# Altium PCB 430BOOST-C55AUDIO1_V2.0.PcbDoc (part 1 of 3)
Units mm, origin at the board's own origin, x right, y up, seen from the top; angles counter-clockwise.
Board outline 50.8 x 84 mm, 4 copper layers (Top Layer, GND, POW, Bottom Layer); 272 components, 169 nets, 833 pads, 607 vias.
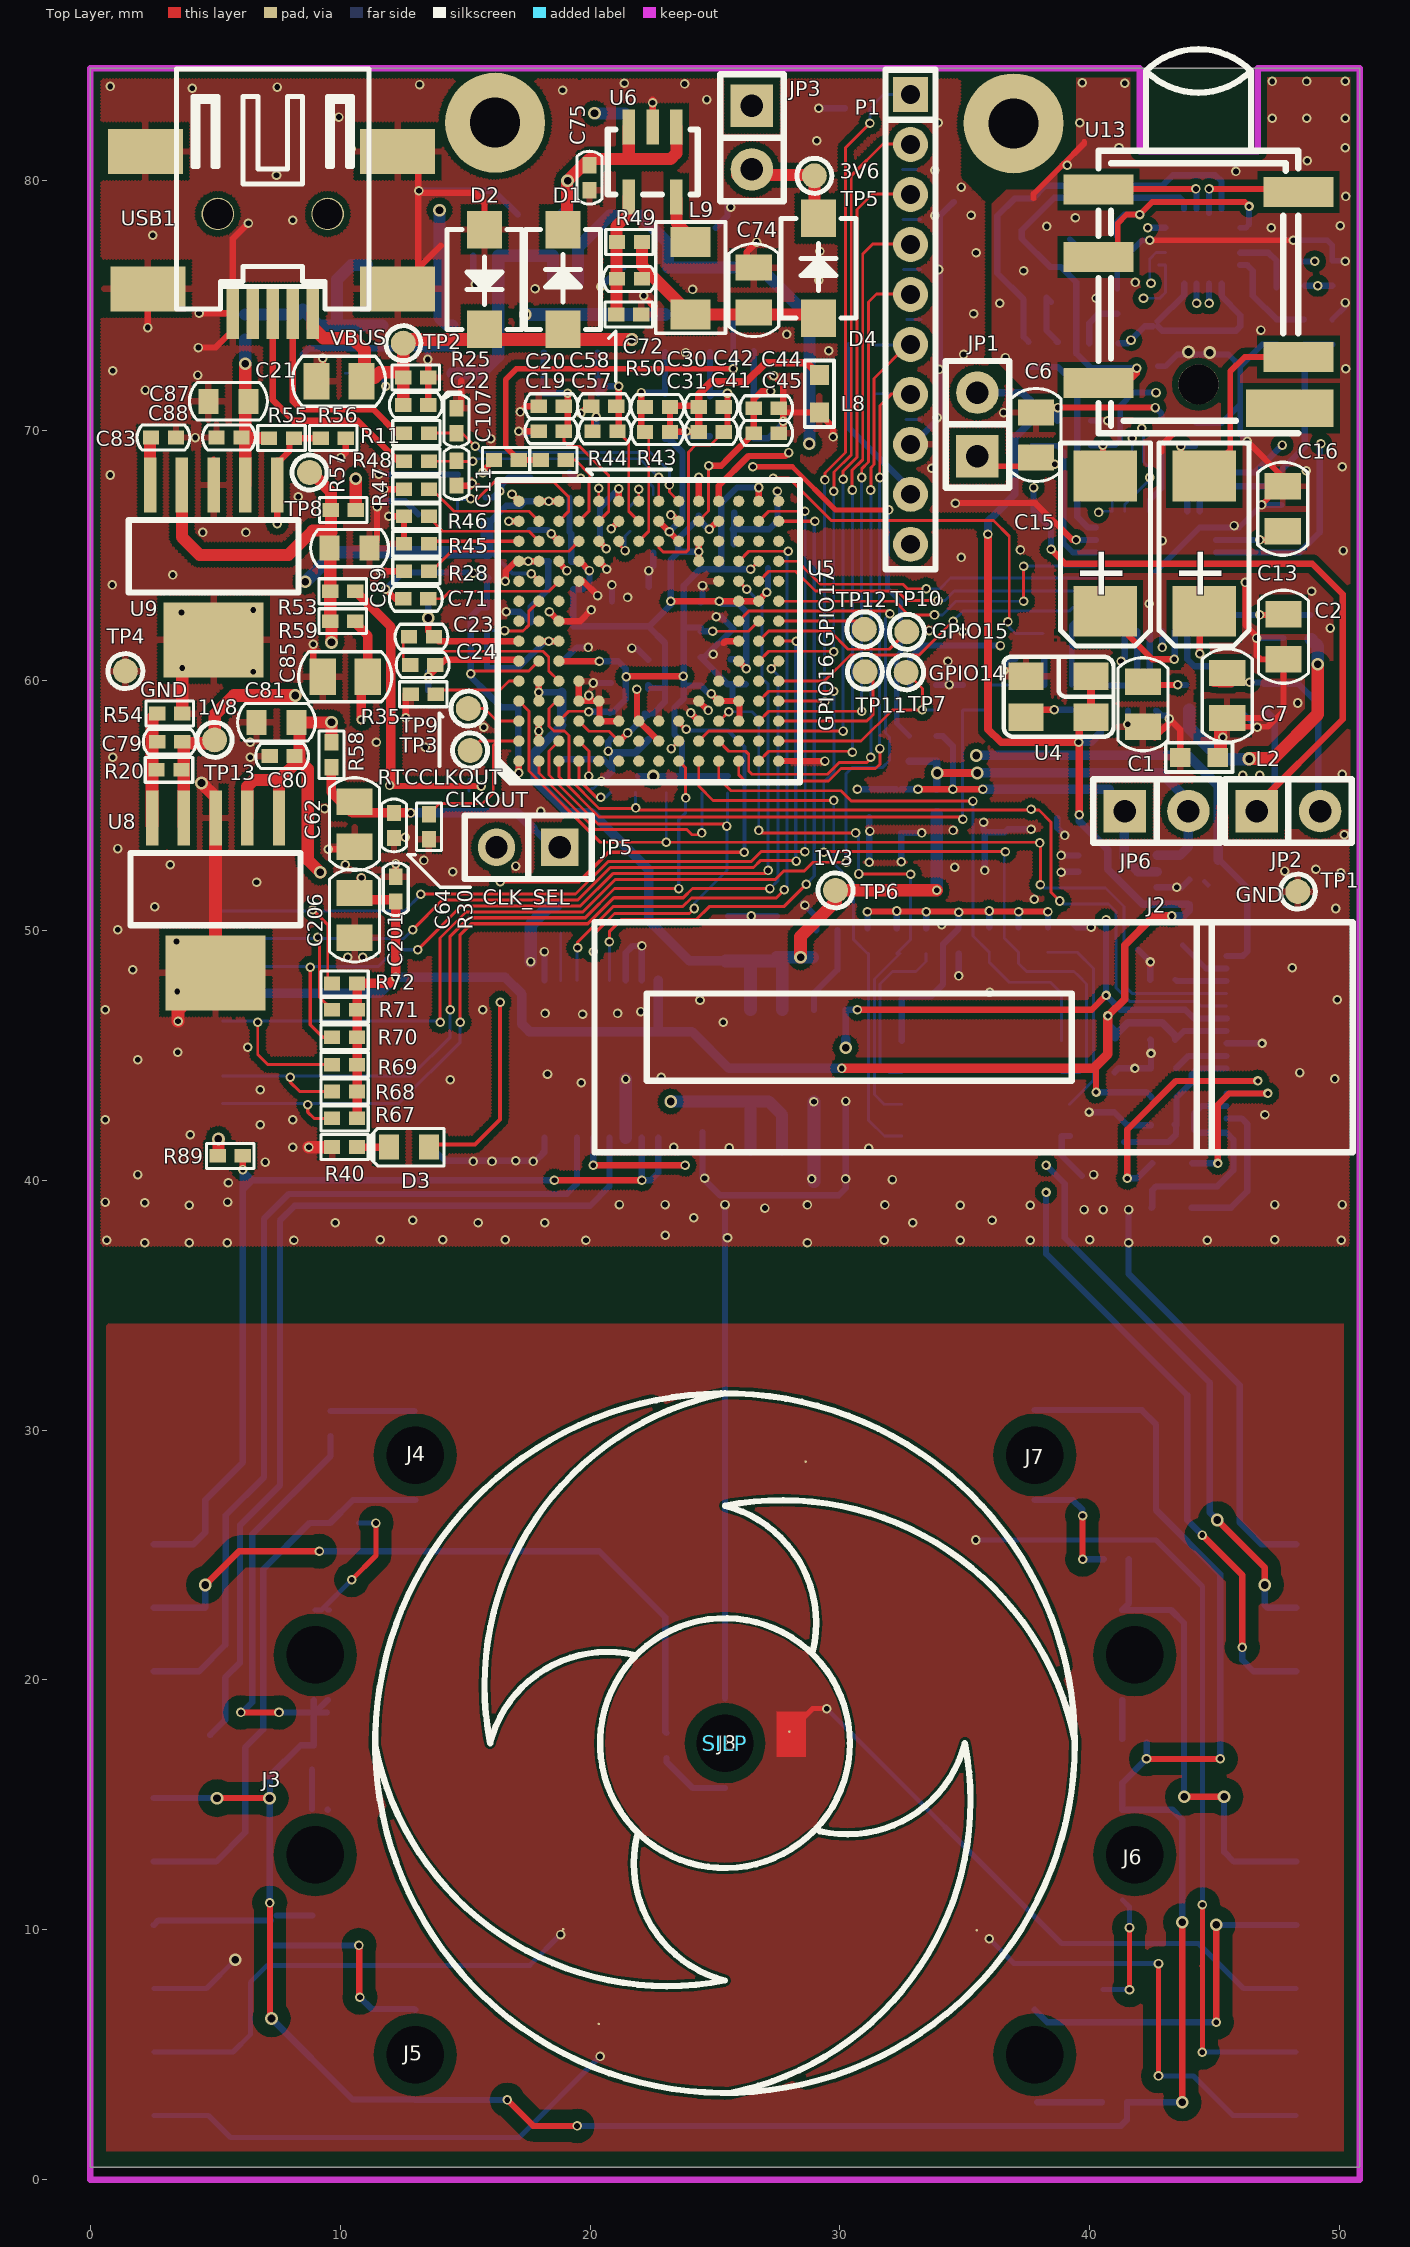
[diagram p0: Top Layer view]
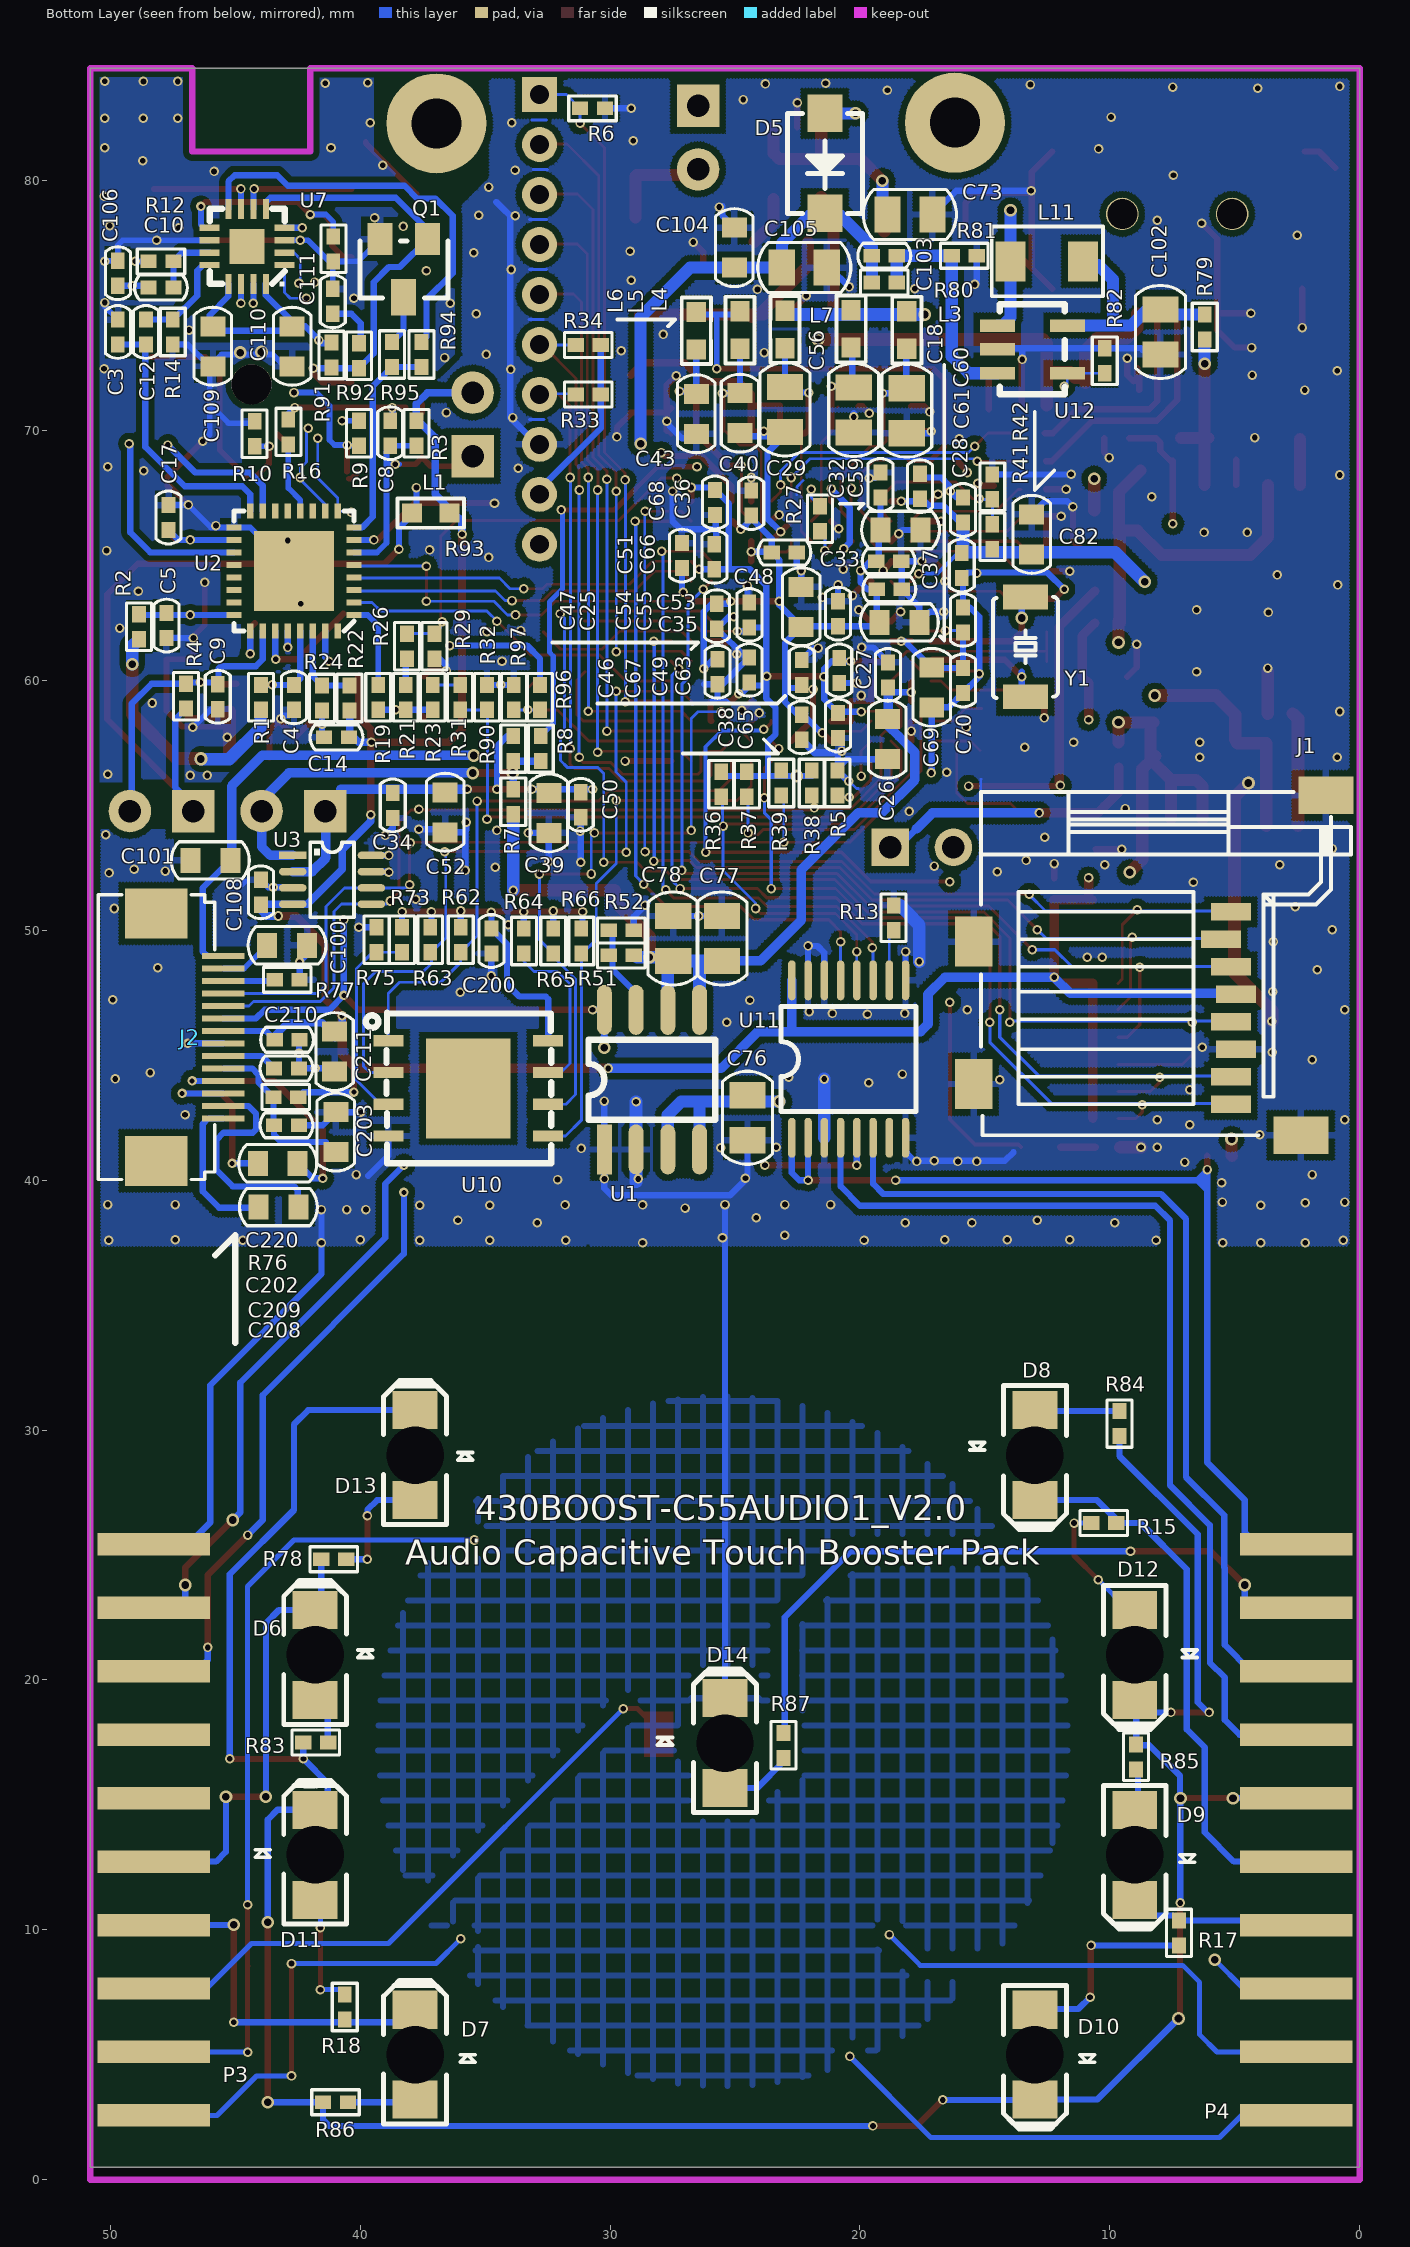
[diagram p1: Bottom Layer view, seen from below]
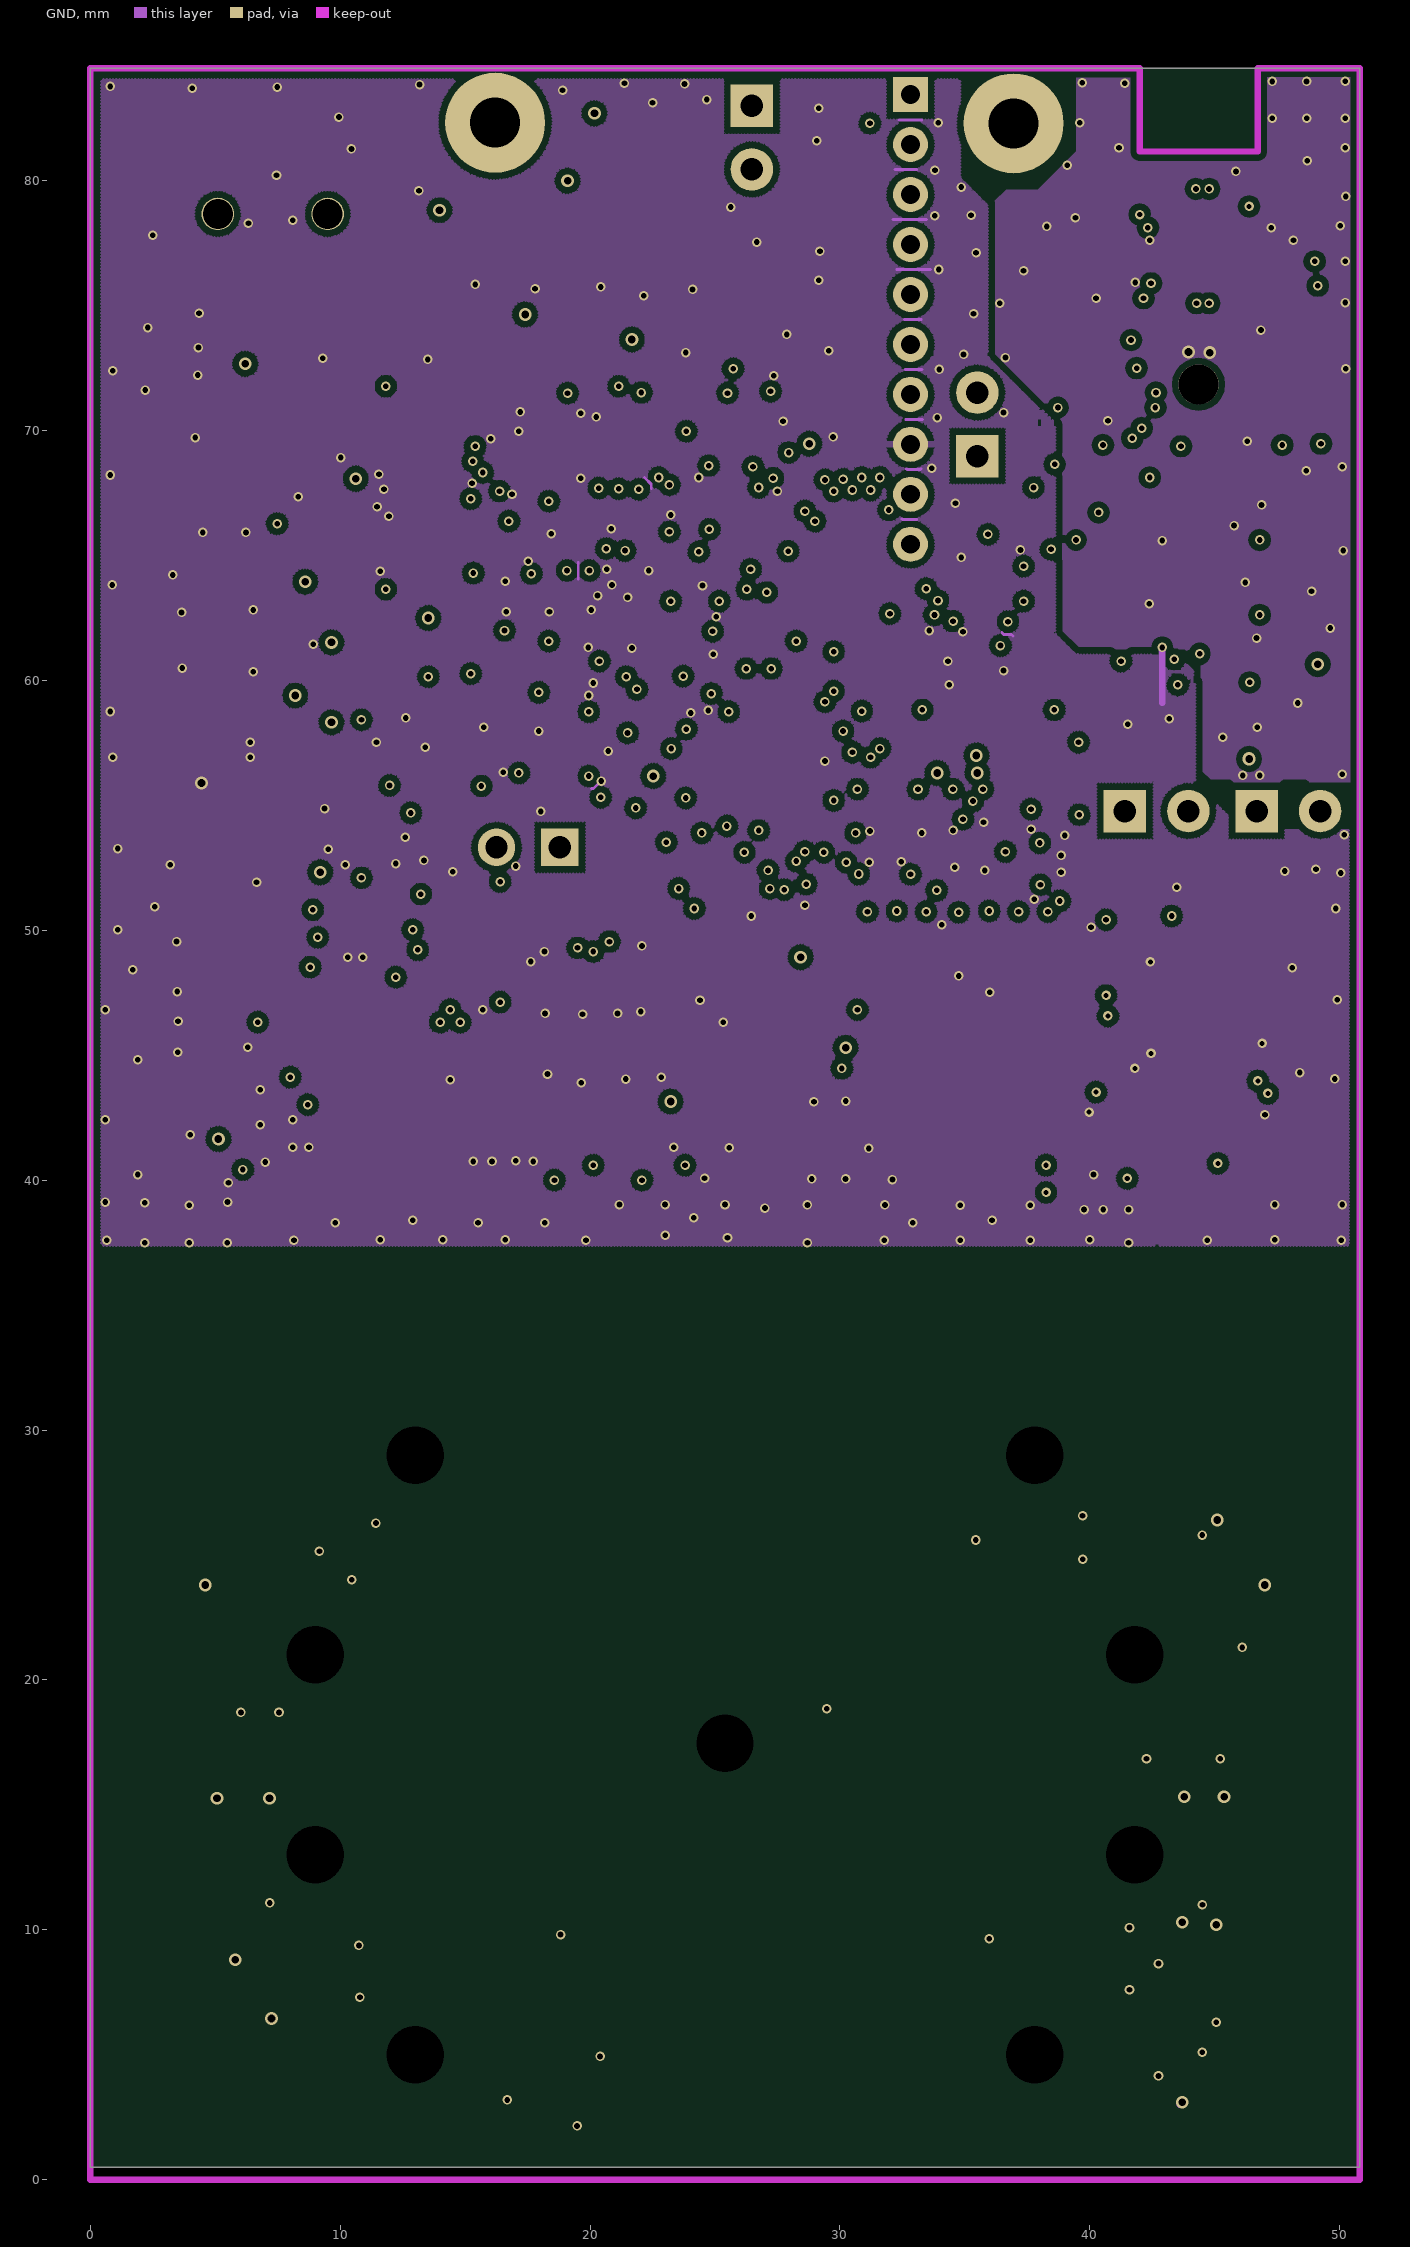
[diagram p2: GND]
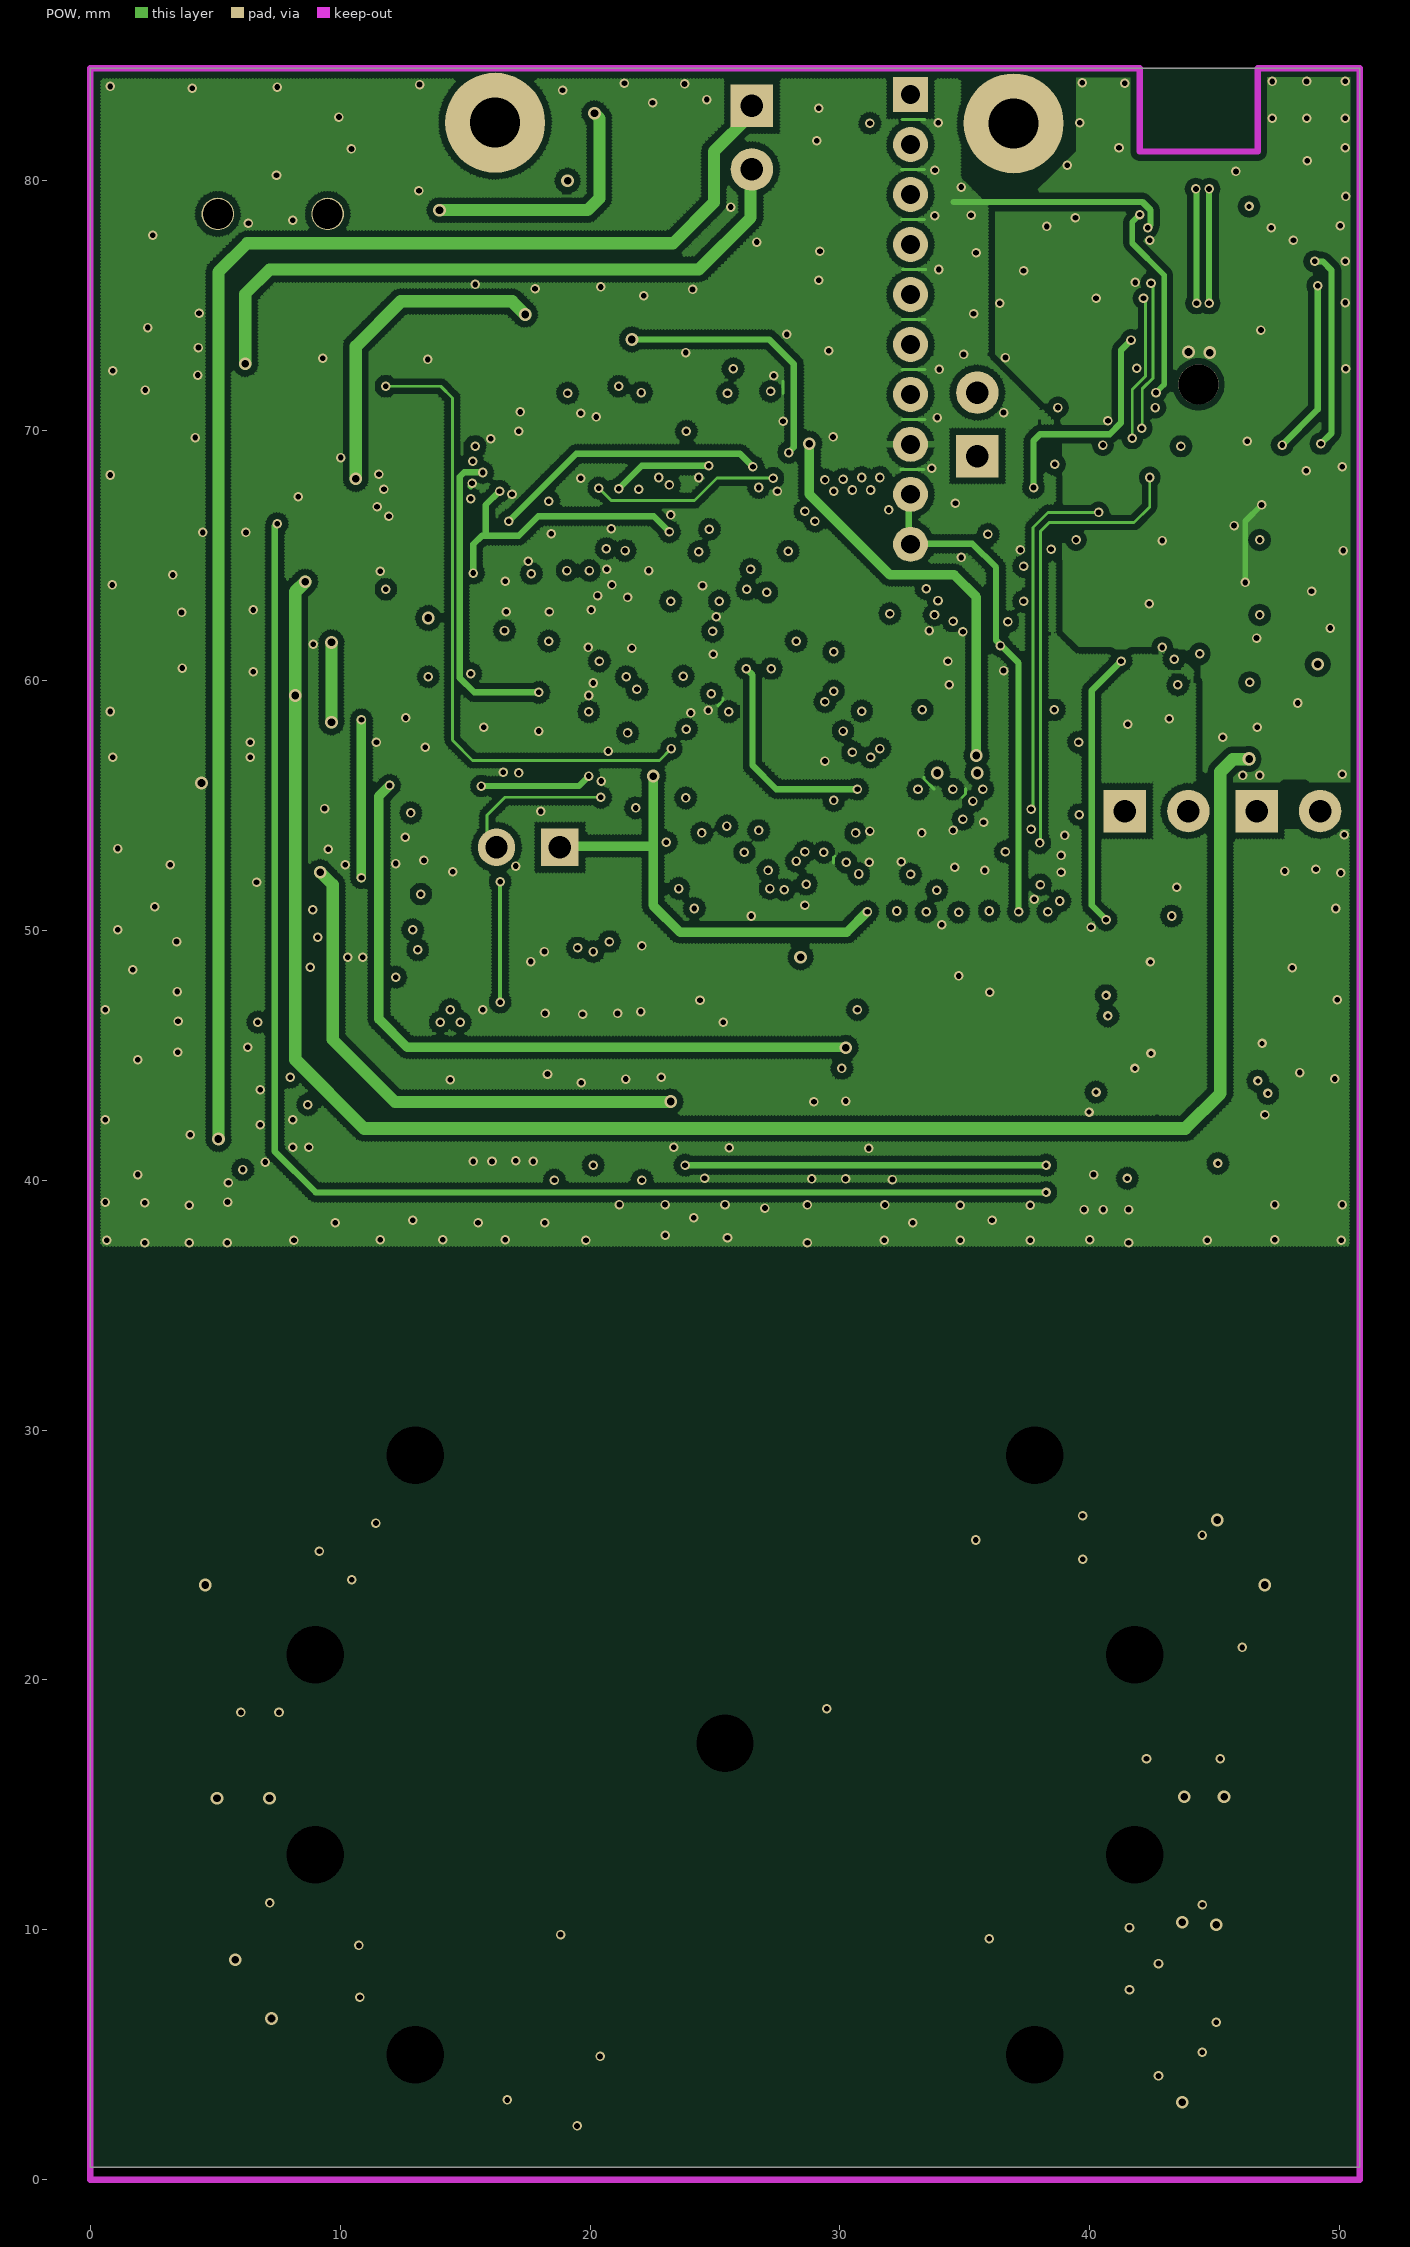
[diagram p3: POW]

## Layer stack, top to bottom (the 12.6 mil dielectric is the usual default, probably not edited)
Top Layer: signal copper 0.0356
Dielectric: core 0.32, FR-4, Dk 4.8
GND: signal copper 0.0356
Dielectric: prepreg 0.32, FR-4, Dk 4.8
POW: signal copper 0.0356
Dielectric: core 0.32, FR-4, Dk 4.8
Bottom Layer: signal copper 0.0356

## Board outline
0,84.5 0,0.5 50.8,0.5 50.8,84.5 0,84.5

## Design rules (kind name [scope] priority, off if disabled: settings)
Clearance Clearance_1 [IsBoard + InPolygon] p1: gap=0.25
Clearance [All] p2: gap=0.114
ComponentClearance [All] p1 off: gap=0.254 collisioncheckmode=3 verticalgap=0.254 showdistances=FALSE
FabricationTestPointUsage TestPointUsage [All] p1: valid=0 allowmultiple=FALSE
FabricationTestpoint Testpoint [(IsPad And (OnTopLayer Or OnBottomLayer))] p1: side=3 testpointundercomponent=TRUE minsize=1.016 maxsize=2.54 preferedsize=1.524 minholesize=0 maxholesize=1.016 preferedholesize=0.813 testpointgrid=0.025 allowsidetop=TRUE allowsidebottom=TRUE usegrid=TRUE gridtolerance=0
Height [All] p1 off: minheight=0 maxheight=25.4 prefheight=12.7
HoleSize [All] p1 off: absolutevalues=TRUE maxlimit=2.54 minlimit=0.025 maxpercent=80.000 minpercent=20.000
HoleToHoleClearance [All] p1 off: gap=0.254 allowstackedmicrovias=TRUE
LayerPairs [All] p1 off: enforce=TRUE
MinimumSolderMaskSliver [All] p1 off: minsoldermaskwidth=0.254
NetAntennae [All] p1 off: netantennaetolerance=0
PolygonConnect PolygonConnect_1 [IsVia + InPolygon] p1: connectstyle=Direct reliefconductorwidth=0.254 reliefentries=4 polygonreliefangle="90 Angle"
PolygonConnect [All] p2: connectstyle=Relief reliefconductorwidth=0.254 reliefentries=4 polygonreliefangle="90 Angle"
RoutingVias [All] p1: holewidth=0.229 width=0.381 viastyle="Through Hole" minholewidth=0.203 minwidth=0.381 maxholewidth=0.406 maxwidth=0.762
SilkToSilkClearance [All] p1 off: silktosilkclearance=0.254
SilkscreenOverComponentPads [All] p1 off: minsilkscreentomaskgap=0.254
SolderMaskExpansion [All] p1: expansion=0.102
Width [All] p1: maxlimit=4 minlimit=0.102 preferedwidth=0.25
17 further rules are at their usual default settings.

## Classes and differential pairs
component class 430BOOST-C55XAUDIO1_AIC3204: C1 C2 C3 C4 C5 C6 C7 C8 C9 C10 C12 C13 C14 C15 C16 C17 C106 D6 D7 D8 D9 D10 D11 D12 D13 D14 J3 J4 J5 J6 J7 J8 JP1 JP2 L1 L2 R1 R2 R3 R4 R9 R10 R12 R14 R15 R16 R17 R18 R19 R21 R22 R23 R24 R78 R83 R84 R85 R86 R87 TP1 U2 U4
component class 430BOOST-C55XAUDIO1_MCU_1: C11 C18 C19 C20 C21 C22 C23 C24 C25 C26 C27 C107 D1 D2 D3 JP5 L3 P1 R5 R6 R11 R25 R26 R27 R28 R29 R30 R31 R32 R33 R34 R35 R36 R37 R38 R39 R40 R48 R96 R97 TP2 TP3 TP7 TP9 TP10 TP11 TP12 U5 USB1 Y1
component class 430BOOST-C55XAUDIO1_MCU_2: C28 C29 C30 C31 C32 C33 C34 C35 C36 C37 C38 C39 C40 C41 C42 C43 C44 C45 C46 C47 C48 C49 C50 C51 C52 C53 C54 C55 C56 C57 C58 C59 C60 C61 C62 C63 C64 C65 C66 C67 C68 C69 C70 C71 C108 JP6 L4 L5 L6 L7 L8 R7 R8 R41 R42 R43 R44 R45 R46 R47 R90 TP4 U3
component class 430BOOST-C55XAUDIO1_Power: C72 C73 C74 C75 C76 C77 C78 C79 C80 C81 C82 C83 C85 C86 C87 C88 C89 D4 JP3 L9 R20 R49 R50 R51 R52 R53 R54 R55 R56 R57 R58 R59 R89 TP5 TP6 TP8 TP13 U1 U6 U8 U9
component class 430BOOST-C55XAUDIO1_SPI_UART: C90 C91 C92 C93 C94 C95 C96 C97 C98 C99 C100 C101 C102 C103 C104 C105 C200 C201 C202 C203 C206 C208 C209 C210 C211 C220 D5 J1 J2 L11 P3 P4 R13 R62 R63 R64 R65 R66 R67 R68 R69 R70 R71 R72 R73 R75 R76 R77 R79 R80 R81 R82 SILP U10 U11 U12
component class 430BOOST-C55XAUDIO1_TS3A225E: C109 C110 C111 Q1 R91 R92 R93 R94 R95 U7 U13

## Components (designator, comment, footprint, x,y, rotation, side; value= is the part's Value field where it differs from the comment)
C1 "10uF" 0805-c 42.125,59.05 r270 top
C2 "10uF" 0805-c 47.75,61.75 r270 top
C3 "NO_POP" 0402-C 49.7,73.95 r270 bottom
C4 "0.1uF" 0402-C 42.65,59.325 r90 bottom
C5 "0.1uF" 0402-C 47.75,62.2 r90 bottom
C6 "10uF" 0805-c 37.85,69.825 r90 top
C7 "10uF" 0805-c 45.5,59.4 r270 top
C8 "0.1uF" 0402-C 38.8,69.9 r270 bottom
C9 "0.1uF" 0402-C 45.7,59.35 r90 bottom
C10 "0.47uF" 0402-C 47.975,75.725 r180 bottom
C11 "22pF" 0402-C 14.65,68.3 r90 top
C12 "0.47uF" 0402-C 48.575,73.95 r90 bottom
C13 "100uF" SMD-C 44.575,65.475 r90 top
C14 "0.1uF" 0402-C 40.95,57.725 r180 bottom
C15 "100uF" SMD-C 40.625,65.475 r90 top
C16 "10uF" 0805-c 47.725,66.875 r90 top
C17 "0.1uF" 0402-C 47.675,66.525 r270 bottom
C18 "10uF" 0805-C 18.125,70.8 r270 bottom
C19 "0.1uF" 0402-C 18.45,69.975 r0 top
C20 "1000pF" 0402-C 18.45,70.975 r0 top
C21 "10uF" 0805-C 9.95,71.975 r180 top
C22 "0.1uF" 0402-C 13.025,71.025 r0 top
C23 "33pF" 0402-C 13.25,61.75 r0 top
C24 "33pF" 0402-C 13.3,60.625 r0 top
C25 "0.1uF" 0402-C 24.425,62.625 r270 bottom
C26 "1uF" 0603-C 18.9,57.65 r90 bottom
C27 "0.1uF" 0402-C 18.875,60.225 r270 bottom
C28 "0.01uF" 0402-C 15.875,62.425 r270 bottom
C29 "10uF" 0805-C 23,70.85 r270 bottom
C30 "0.1uF" 0402-C 22.7,70.95 r180 top
C31 "1000pF" 0402-C 22.7,69.95 r180 top
C32 "0.1uF" 0402-C 19.175,67.825 r270 bottom
C33 "0.1uF" 0402-C 18.85,64.775 r0 bottom
C34 "0.1uF" 0402-C 38.7,55 r90 bottom
C35 "1uF" 0603-C 18.425,62.325 r0 bottom
C36 "0.01uF" 0402-C 24.35,67.1 r270 bottom
C37 "1uF" 0603-C 18.375,66.025 r0 bottom
C38 "0.01uF" 0402-C 22.325,58.125 r90 bottom
C39 "1uF" 0603-C 32.45,54.7 r90 bottom
C40 "1uF" 0603-C 24.8,70.7 r90 bottom
C41 "0.1uF" 0402-C 24.85,69.95 r0 top
C42 "0.01uF" 0402-C 24.85,70.95 r0 top
C43 "1uF" 0603-C 26.55,70.675 r90 bottom
C44 "0.1uF" 0402-C 27.05,70.9 r180 top
C45 "1000pF" 0402-C 27.05,69.9 r180 top
C46 "0.1uF" 0402-C 25.7,60.35 r90 bottom
C47 "0.1uF" 0402-C 25.725,62.575 r90 bottom
C48 "0.1uF" 0402-C 23.025,65.125 r0 bottom
C49 "0.1uF" 0402-C 22.325,60.325 r270 bottom
C50 "0.1uF" 0402-C 31.175,55.025 r90 bottom
C51 "0.01uF" 0402-C 27.125,65 r270 bottom
C52 "1uF" 0603-C 36.6,54.725 r90 bottom
C53 "0.01uF" 0402-C 18.825,63.65 r0 bottom
C54 "1uF" 0603-C 22.35,62.95 r270 bottom
C55 "0.01uF" 0402-C 20.875,62.675 r270 bottom
C56 "10uF" 0805-C 20.25,70.825 r270 bottom
C57 "0.1uF" 0402-C 20.6,69.975 r0 top
C58 "1000pF" 0402-C 20.55,70.975 r0 top
C59 "0.1uF" 0402-C 17.6,67.775 r270 bottom
C60 "0.1uF" 0402-C 15.875,66.825 r270 bottom
C61 "0.1uF" 0402-C 15.925,64.6 r90 bottom
C62 "10uF" 0805-C 10.575,54.25 r270 top
C63 "0.1uF" 0402-C 20.825,60.4 r90 bottom
C64 "0.1uF" 0402-C 12.15,54.2 r90 top
C65 "0.1uF" 0402-C 20.875,58.2 r90 bottom
C66 "0.1uF" 0402-C 25.825,64.95 r270 bottom
C67 "0.1uF" 0402-C 24.425,60.425 r270 bottom
C68 "0.1uF" 0402-C 25.8,67.125 r90 bottom
C69 "1uF" 0603-C 17.125,59.725 r90 bottom
C70 "0.1uF" 0402-C 15.875,60 r90 bottom
C71 "0.1uF" 0402-C 13.025,63.275 r0 top
C72 "2200pF" 0402-C 21.575,76.075 r0 top
C73 "4.7uF" 0805-c 18,78.65 r180 bottom
C74 "10uF" 0805-c 26.55,75.625 r90 top
C75 "0.1uF" 0402-C 19.975,80.125 r90 top
C76 "4.7uF" 0805-c 24.5,42.5 r270 bottom
C77 "4.7uF" 0805-c 25.525,49.675 r90 bottom
C78 "4.7uF" 0805-c 27.475,49.675 r90 bottom
C79 "33pF" 0402-C 3.175,57.55 r0 top
C80 "0.1uF" 0402-C 7.675,56.975 r0 top
C81 "1uF" 0603-C 7.45,58.325 r0 top
C82 "1uF" 0603-C 13.125,65.85 r270 bottom
C83 "0.01uF" 0402-C 2.925,69.725 r180 top
C85 "4.7uF" 0805-c 10.2,60.15 r180 top
C87 "1uF" 0603-C 5.525,71.175 r0 top
C88 "0.1uF" 0402-C 5.55,69.725 r0 top
C89 "1uF" 0603-C 10.375,65.3 r180 top
C100 "2.2uF" 0603-c 42.925,49.4 r180 bottom
C101 "2.2uF" 0603-c 46,52.8 r0 bottom
C102 "10uF" 0805-c 7.975,73.95 r270 bottom
C103 "10pF" 0402-C 19.025,77 r0 bottom
C104 "1uF" 0603-C 25.025,77.325 r270 bottom
C105 "10uF/16V" 0805-c 22.225,76.525 r180 bottom
C106 "NO_POP" 0402-C 49.7,76.3 r270 bottom
C107 "22pF" 0402-C 14.65,70.4 r270 top
C108 "0.1uF" 0402-C 43.975,51.525 r270 bottom
C109 "1uF" 0603-C 45.9,73.375 r90 bottom
C110 "1uF" 0603-C 42.725,73.375 r90 bottom
C111 "0.47uF" 0402-C 41.1,75.175 r270 bottom
C200 "0.1uF" 0402-C 34.75,49.575 r90 bottom
C201 "0.1uF" 0402-C 12.225,51.65 r270 top
C202 "0.1uF" 0402-C 42.95,42.2 r0 bottom
C203 "1uF" 0603-C 40.975,41.925 r270 bottom
C206 "10uF" 0805-c 10.575,50.6 r270 top
C208 "1uF" 0603-C 43.275,38.925 r0 bottom
C209 "1uF" 0603-C 43.3,40.675 r0 bottom
C210 "0.1uF" 0402-C 42.925,45.625 r0 bottom
C211 "1uF" 0603-C 41.025,45.15 r90 bottom
C220 "0.022uF" 0402-C 42.95,44.475 r0 bottom
D1 "MBR0520" SOD-123-1 18.925,76.05 r90 top
D2 "6.2V" SOD-123-1 15.775,76.05 r270 top
D3 "LED_GREEN" 0603-1 12.75,41.325 r180 top
D4 "MBR0520" SOD-123-1 29.15,76.5 r90 top
D5 "MBR0520" SOD-123-1 21.4,80.7 r270 bottom
D6 "LED8" 1206-W 41.8,21 r90 bottom locked
D7 "LED7" 1206-W 37.8,5 r90 bottom locked
D8 "LED5" 1206-W 13,29 r270 bottom
D9 "LED6" 1206-W 9,13 r270 bottom locked
D10 "LED2" 1206-W 13,5 r270 bottom
D11 "LED3" 1206-W 41.8,13 r90 bottom locked
D12 "LED1" 1206-W 9,21 r270 bottom
D13 "LED4" 1206-W 37.8,29 r90 bottom
D14 "LED9" 1206-W 25.4,17.47 r90 bottom locked
J1 "SD CARD" microsd-TF2 5.15,43.04 r270 bottom
J2 "OSD9616" LCD-UG-9616TLBBG02 49.275,45.725 r0 top locked
J3 "PAD" SIP1-TEST#1 6.52,16.15 r90 top
J4 "PAD" SIP1-TEST#2 18.92,10.02 r90 top
J5 "PAD" SIP1-TEST#2 20.35,6.23 r90 top
J6 "PAD" SIP1-TEST#2 35.48,9.98 r90 top
J7 "PAD" SIP1-TEST#2 28.63,28.74 r90 top
J8 "PAD" SIP1-TEST#2 27.98,17.93 r90 top
JP1 "JUMPER" SIP2-2.54#1 35.5,70.25 r270 top
JP2 "JUMPER" SIP2-2.54#1 47.95,54.775 r180 top
JP3 "JUMPER" SIP2-2.54#1 26.475,81.725 r90 top
JP5 "JUMPER" SIP2-2.54#2 17.525,53.325 r0 top
JP6 "NO_POP" SIP2-2.54#1 42.675,54.775 r180 top
L1 "BLM21AG151SN1D" 0603-L 37.175,66.7 r0 bottom
L2 "BLM21AG151SN1D" 0603-L 44.375,56.925 r0 top
L3 "BLM18AG601SN1D" 0603-L 18.125,74.025 r270 bottom
L4 "BLM18AG601SN1D" 0603-L 23,74.05 r270 bottom
L5 "BLM18AG601SN1D" 0603-L 24.8,74.025 r270 bottom
L6 "BLM18AG601SN1D" 0603-L 26.55,74 r270 bottom
L7 "BLM18AG601SN1D" 0603-L 20.35,74.075 r270 bottom
L8 "BLM18AG601SN1D" 0603-L 29.175,71.475 r90 top
L9 "2.2uH" VLF3010A 24.025,76.1 r270 top
L11 "2.2uH" VLF3010A 12.525,76.775 r0 bottom
P1 "NO_POP" SIP10-2.0 32.825,74.45 r90 top
P3 "Header 10" SIP10-2.54MM-SMD 48.26,14 r0 bottom
P4 "Header 10" SIP10-2.54MM-SMD 2.54,14 r0 bottom
Q1 "APM2309A-TRL" SOT-23-3P 38.25,76.5 r0 bottom
R1 "NO_POP" 0402-R 43.975,59.325 r90 bottom
R2 "NO_POP" 0402-R 48.85,62.15 r270 bottom
R3 "0" 0402-R 37.75,69.9 r270 bottom
R4 "0" 0402-R 46.975,59.375 r270 bottom
R5 "10K" 0402-R 20.9,55.9 r270 bottom
R6 "4.7K" 0402-R 30.7,82.9 r0 bottom
R7 "0" 0402-R 33.875,55.15 r90 bottom
R8 "NO_POP" 0402-R 32.775,57.275 r270 bottom
R9 "47K" 0402-R 40.05,69.9 r270 bottom
R10 "47K" 0402-R 44.225,69.875 r270 bottom
R11 "33" 0402-R 13.05,69.9 r180 top
R12 "2.2K" 0402-R 47.975,76.775 r0 bottom
R13 "10K" 0402-R 18.65,50.5 r270 bottom
R14 "1K" 0402-R 47.5,73.95 r90 bottom
R15 "330" 0402-R 10.24,26.28 r180 bottom
R16 "4.7K" 0402-R 42.875,69.95 r270 bottom
R17 "330" 0402-R 7.225,9.875 r90 bottom
R18 "330" 0402-R 40.62,6.91 r270 bottom
R19 "100" 0402-R 39.275,59.325 r270 bottom
R20 "14K  1%" 0402-R 3.15,56.425 r0 top
R21 "0" 0402-R 38.175,59.325 r90 bottom
R22 "4.7K" 0402-R 40.425,59.3 r90 bottom
R23 "0" 0402-R 37.1,59.325 r90 bottom
R24 "NO_POP" 0402-R 41.525,59.3 r270 bottom
R25 "100K" 0402-R 13.025,72.125 r180 top
R26 "0" 0402-R 38.125,61.375 r90 bottom
R27 "10K  1%" 0402-R 21.6,66.475 r90 bottom
R28 "0" 0402-R 13.05,64.375 r0 top
R29 "NO_POP" 0402-R 37.025,61.375 r90 bottom
R30 "10K" 0402-R 13.55,54.15 r90 top
R31 "0" 0402-R 36,59.325 r90 bottom
R32 "NO_POP" 0402-R 34.925,59.325 r270 bottom
R33 "10K" 0402-R 30.875,71.45 r180 bottom
R34 "10K" 0402-R 30.875,73.425 r180 bottom
R35 "10K" 0402-R 13.325,59.45 r0 top
R36 "100K" 0402-R 25.55,55.85 r90 bottom
R37 "100K" 0402-R 24.525,55.85 r90 bottom
R38 "10K" 0402-R 21.925,55.9 r90 bottom
R39 "10K" 0402-R 23.15,55.9 r90 bottom
R40 "220" 0402-R 10.175,41.325 r0 top
R41 "10K" 0402-R 14.7,65.75 r270 bottom
R42 "NO_POP" 0402-R 14.7,67.75 r270 bottom
R43 "NO_POP" 0402-R 18.525,68.825 r0 top
R44 "0" 0402-R 16.65,68.825 r0 top
R45 "0" 0402-R 13.05,65.475 r180 top
R46 "0" 0402-R 13.05,66.575 r180 top
R47 "10K" 0402-R 13.05,67.65 r180 top
R48 "33" 0402-R 13.05,68.775 r180 top
R49 "18.2K  1%" 0402-R 21.575,77.55 r0 top
R50 "3.3K  1%" 0402-R 21.55,74.65 r180 top
R51 "10.7K  1%" 0402-R 29.55,49 r180 bottom
R52 "110K  1%" 0402-R 29.55,50 r0 bottom
R53 "250K" 0402-R 10.1,63.575 r180 top
R54 "30K  1%" 0402-R 3.175,58.675 r0 top
R55 "NOP_POP_4.7K" 0402-R 7.65,69.7 r180 top
R56 "4.7K" 0402-R 9.725,69.7 r180 top
R57 "0" 0402-R 10.125,66.825 r0 top
R58 "0" 0402-R 9.65,57.025 r270 top
R59 "0" 0402-R 10.1,62.375 r0 top
R62 "NO_POP" 0402-R 35.975,49.625 r270 bottom
R63 "NO_POP" 0402-R 37.2,49.625 r270 bottom
R64 "10K" 0402-R 33.45,49.575 r90 bottom
R65 "NO_POP" 0402-R 32.275,49.575 r270 bottom
R66 "NO_POP" 0402-R 31.15,49.575 r270 bottom
R67 "10K" 0402-R 10.175,42.475 r0 top
R68 "10K" 0402-R 10.175,43.55 r0 top
R69 "NO_POP" 0402-R 10.175,44.625 r0 top
R70 "10K" 0402-R 10.175,45.725 r0 top
R71 "10K" 0402-R 10.175,46.825 r0 top
R72 "10K" 0402-R 10.175,47.875 r0 top
R73 "10K" 0402-R 38.325,49.625 r270 bottom
R75 "NO_POP" 0402-R 39.35,49.625 r270 bottom
R76 "NO_POP" 0402-R 42.975,43.325 r180 bottom
R77 "392K  1%" 0402-R 42.925,48.025 r180 bottom
R78 "330" 0402-R 41.06,24.83 r0 bottom
R79 "0" 0402-R 6.2,74.15 r90 bottom
R80 "1.6M  1%" 0402-R 19.025,75.925 r0 bottom
R81 "180K  1%" 0402-R 15.825,77 r0 bottom
R82 "10K" 0402-R 10.2,72.8 r270 bottom
R83 "330" 0402-R 41.78,17.5 r180 bottom
R84 "330" 0402-R 9.61,30.26 r90 bottom
R85 "330" 0402-R 8.95,16.92 r270 bottom
R86 "330" 0402-R 40.99,3.1 r180 bottom
R87 "330" 0402-R 23.06,17.38 r90 bottom
R89 "0" 0402-R 5.6,40.975 r0 top
R90 "1  1%" 0402-R 33.875,57.275 r90 bottom
R91 "100K" 0402-R 41.15,73.025 r90 bottom
R92 "220K" 0402-R 40.05,73 r270 bottom
R93 "10K" 0402-R 41.075,77.275 r90 bottom
R94 "20K" 0402-R 37.55,73.05 r270 bottom
R95 "39.2K" 0402-R 38.725,73.05 r270 bottom
R96 "NO_POP" 0402-R 32.8,59.325 r90 bottom
R97 "NO_POP" 0402-R 33.85,59.325 r90 bottom
SILP "SIP" PAD-28MM 25.4,17.47 r0 top locked
TP1 "GND" SIP1-TEST#3 48.325,51.55 r0 top
TP2 "VBUS" SIP1-TEST#3 12.525,73.5 r270 top
TP3 "CLKOUT" SIP1-TEST#3 15.2,57.2 r0 top
TP4 "GND" SIP1-TEST#3 1.4,60.375 r180 top
TP5 "VCC_3V6_TP" SIP1-TEST#3 28.975,80.2 r180 top
TP6 "VCC_1V3_TP" SIP1-TEST#3 29.825,51.6 r270 top
TP7 "TextPoint" SIP1-TEST#3 32.65,60.325 r0 top
TP8 "VCC_3V3_TP" SIP1-TEST#3 8.775,68.325 r180 top
TP9 "RTC_CLKOUT" SIP1-TEST#3 15.125,58.875 r90 top
TP10 "TextPoint" SIP1-TEST#3 32.675,61.95 r0 top
TP11 "TextPoint" SIP1-TEST#3 31,60.35 r0 top
TP12 "TextPoint" SIP1-TEST#3 30.975,62.05 r0 top
TP13 "VCC_1V8_TP" SIP1-TEST#3 4.975,57.625 r90 top
U1 "TPS77801" SOIC-8P 28.325,44.025 r180 bottom
U2 "TLV320AIC3204IRHBT" QFN-32P-0.5MM 40.25,62.625 r90 bottom
U3 "INA219IDCN" SOT-23-8P 41.125,52.025 r270 bottom
U4 "DSX321G 12MHZ" SMD3225-4 38.75,59.35 r180 top
U5 "TMS320C5535" BGA-N144-0.8MM 22.35,61.975 r0 top locked
U6 "TPS62260DDCT" SOT-23-5P 22.5,80.75 r180 top
U7 "TS3A225E" QFN-16P-0.5MM 44.525,77.375 r90 bottom
U8 "TPS79501DCQ" SOT-223-6 7.55,54.5 r180 top
U9 "TPS79533DCQ" SOT-223-6 7.475,67.825 r180 top
U10 "SST25VF016B" son-8p 35.675,43.675 r180 bottom
U11 "SN74AVC4T245" TSSOP-16P 20.45,44.85 r180 bottom
U12 "TPS61041DBV" SOT-23-5P 13.1,73.25 r270 bottom
U13 "Audio  Line Input" KJ-355-X1 44.35,84.4 r270 top
USB1 "USB-MINI--F" USB-MIN-F 7.25,77.925 r0 top locked
Y1 "32.768KHz" SMD4015-2 13.375,61.35 r90 bottom

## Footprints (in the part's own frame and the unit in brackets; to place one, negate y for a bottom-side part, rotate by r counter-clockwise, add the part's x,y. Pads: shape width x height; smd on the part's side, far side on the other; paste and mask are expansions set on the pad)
0402-C [mm]
  rect 0.65x0.55 smd: 1(-0.5,0) 2(0.5,0)
  silkscreen extent -1.06,-0.5 1.06,0.5
0402-R [mm]
  rect 0.65x0.55 smd: 1(-0.5,0) 2(0.5,0)
  silkscreen extent -0.95,-0.5 0.95,0.5
0603-1 [mm]
  rect 0.8x1 smd: 1(-0.8,0) 2(0.8,0)
  silkscreen extent -1.4,-0.75 1.5,0.75
0603-C [mm]
  rect 0.8x1 smd: 1(-0.8,0) 2(0.8,0)
  silkscreen extent -1.56,-0.75 1.56,0.75
0603-c [mm]
  rect 0.8x1 smd: 1(-0.8,0) 2(0.8,0)
  silkscreen extent -1.56,-0.75 1.56,0.75
0603-L [mil]
  rect 32x30 smd: 1(-29.5,0) 2(29.5,0)
  silkscreen extent -52,-23 52,23
0805-c [mm]
  rect 1.05x1.45 smd: 1(-0.9,0) 2(0.9,0)
  silkscreen extent -1.86,-1 1.86,1
0805-C [mm]
  rect 1.05x1.45 smd: 1(-0.9,0) 2(0.9,0)
  silkscreen extent -1.86,-1 1.86,1
1206-W [mm]
  rect 1.524x1.8 smd: 1(-1.8,0) 2(1.8,0)
  round 0 hole 2.3 unplated: ""(0,0)
  silkscreen extent -2.78,-1.26 2.97,1.26
BGA-N144-0.8MM [mm]
  round 0.45 smd: A1(-5.2,-5.2) A2(-5.2,-4.4) A3(-5.2,-3.6) A4(-5.2,-2.8) A5(-5.2,-2) A6(-5.2,-1.2) A7(-5.2,-0.4) A8(-5.2,0.4) A9(-5.2,1.2) A10(-5.2,2) A11(-5.2,2.8) A12(-5.2,3.6) A13(-5.2,4.4) A14(-5.2,5.2) B1(-4.4,-5.2) B2(-4.4,-4.4) B3(-4.4,-3.6) B4(-4.4,-2.8) B5(-4.4,-2) B6(-4.4,-1.2) B7(-4.4,-0.4) B8(-4.4,0.4) B9(-4.4,1.2) B10(-4.4,2) B11(-4.4,2.8) B12(-4.4,3.6) B13(-4.4,4.4) B14(-4.4,5.2) C1(-3.6,-5.2) C2(-3.6,-4.4) C3(-3.6,-3.6) C4(-3.6,-2.8) C5(-3.6,-2) C6(-3.6,-1.2) C7(-3.6,-0.4) C8(-3.6,0.4) C9(-3.6,1.2) C10(-3.6,2) C11(-3.6,2.8) C12(-3.6,3.6) C13(-3.6,4.4) C14(-3.6,5.2) D1(-2.8,-5.2) D2(-2.8,-4.4) D3(-2.8,-3.6) D4(-2.8,-2.8) D5(-2.8,-2) D10(-2.8,2) D11(-2.8,2.8) D12(-2.8,3.6) D13(-2.8,4.4) D14(-2.8,5.2) E1(-2,-5.2) E2(-2,-4.4) E3(-2,-3.6) E4(-2,-2.8) E11(-2,2.8) E12(-2,3.6) E13(-2,4.4) E14(-2,5.2) F1(-1.2,-5.2) F2(-1.2,-4.4) F3(-1.2,-3.6) F12(-1.2,3.6) F13(-1.2,4.4) F14(-1.2,5.2) G1(-0.4,-5.2) G2(-0.4,-4.4) G3(-0.4,-3.6) G12(-0.4,3.6) G13(-0.4,4.4) G14(-0.4,5.2) H1(0.4,-5.2) H2(0.4,-4.4) H3(0.4,-3.6) H12(0.4,3.6) H13(0.4,4.4) H14(0.4,5.2) J1(1.2,-5.2) J2(1.2,-4.4) J3(1.2,-3.6) J12(1.2,3.6) J13(1.2,4.4) J14(1.2,5.2) K1(2,-5.2) K2(2,-4.4) K3(2,-3.6) K4(2,-2.8) K11(2,2.8) K12(2,3.6) K13(2,4.4) K14(2,5.2) L1(2.8,-5.2) L2(2.8,-4.4) L3(2.8,-3.6) L4(2.8,-2.8) L5(2.8,-2) L10(2.8,2) L11(2.8,2.8) L12(2.8,3.6) L13(2.8,4.4) L14(2.8,5.2) M1(3.6,-5.2) M2(3.6,-4.4) M3(3.6,-3.6) M4(3.6,-2.8) M5(3.6,-2) M6(3.6,-1.2) M7(3.6,-0.4) M8(3.6,0.4) M9(3.6,1.2) M10(3.6,2) M11(3.6,2.8) M12(3.6,3.6) M13(3.6,4.4) M14(3.6,5.2) N1(4.4,-5.2) N2(4.4,-4.4) N3(4.4,-3.6) N4(4.4,-2.8) N5(4.4,-2) N6(4.4,-1.2) N7(4.4,-0.4) N8(4.4,0.4) N9(4.4,1.2) N10(4.4,2) N11(4.4,2.8) N12(4.4,3.6) N13(4.4,4.4) N14(4.4,5.2) P1(5.2,-5.2) P2(5.2,-4.4) P3(5.2,-3.6) P4(5.2,-2.8) P5(5.2,-2) P6(5.2,-1.2) P7(5.2,-0.4) P8(5.2,0.4) P9(5.2,1.2) P10(5.2,2) P11(5.2,2.8) P12(5.2,3.6) P13(5.2,4.4) P14(5.2,5.2)
  silkscreen extent -6.05,-6.05 6.05,6.05
KJ-355-X1 [mm]
  rect 1.2x2.8 smd: 1(4.75,-4) 2(4.85,4) 3(7.45,-4) 4(11.45,4) 5(12.5,-4)
  rect 1.5x3.5 smd: 6(13.5,3.65)
  round 1.6 hole 1.6: ""(12.55,0)
  silkscreen extent -0.87,-4 14.5,4
LCD-UG-9616TLBBG02 [mm]
  rect 2.5x2 smd far side: 0(-1.12,-4.95) 0(-1.12,4.95)
  rect 1.7x0.25 smd far side: 1(-3.8,-3.25) 2(-3.8,-2.75) 3(-3.8,-2.25) 4(-3.8,-1.75) 5(-3.8,-1.25) 6(-3.8,-0.75) 7(-3.8,-0.25) 8(-3.8,0.25) 9(-3.8,0.75) 10(-3.8,1.25) 11(-3.8,1.75) 12(-3.8,2.25) 13(-3.8,2.75) 14(-3.8,3.25)
  silkscreen extent -29.1,-4.6 1.25,4.6
microsd-TF2 [mm]
  rect 0.7x1.6 smd: 1(-7.7,0) 2(-6.6,-0.4) 3(-5.5,0) 4(-4.4,0.2) 5(-3.3,0) 6(-2.2,0.2) 7(-1.1,0) 8(0,0)
  rect 2x1.5 smd: 9(-0.81,-10.3) 10(-6.51,-10.3)
  rect 1.5x2.2 smd: 11(-12.36,3.8) 12(1.24,2.8)
  silkscreen extent -12.5,-10 1.24,4.8
PAD-28MM [mm]
  silkscreen extent -14,-14 14,14
QFN-16P-0.5MM [mm]
  rect 1.4x1.4 smd: 0(0,0)
  rect 0.25x0.8 smd: 1(-0.75,-1.5) 2(-0.25,-1.5) 3(0.25,-1.5) 4(0.75,-1.5) 9(0.75,1.5) 10(0.25,1.5) 11(-0.25,1.5) 12(-0.75,1.5)
  rect 0.8x0.25 smd: 5(1.5,-0.75) 6(1.5,-0.25) 7(1.5,0.25) 8(1.5,0.75) 13(-1.5,0.75) 14(-1.5,0.25) 15(-1.5,-0.25) 16(-1.5,-0.75)
  silkscreen extent -1.6,-1.5 1.5,1.5
QFN-32P-0.5MM [mm]
  rect 0.25x0.6 smd: 1(0,0) 2(0.5,0) 3(1,0) 4(1.5,0) 5(2,0) 6(2.5,0) 7(3,0) 8(3.5,0) 17(3.5,4.8) 18(3,4.8) 19(2.5,4.8) 20(2,4.8) 21(1.5,4.8) 22(1,4.8) 23(0.5,4.8) 24(0,4.8)
  rect 0.6x0.25 smd: 9(4.15,0.65) 10(4.15,1.15) 11(4.15,1.65) 12(4.15,2.15) 13(4.15,2.65) 14(4.15,3.15) 15(4.15,3.65) 16(4.15,4.15) 25(-0.65,4.15) 26(-0.65,3.65) 27(-0.65,3.15) 28(-0.65,2.65) 29(-0.65,2.15) 30(-0.65,1.65) 31(-0.65,1.15) 32(-0.65,0.65)
  rect 3.2x3.2 smd: 33(1.75,2.4)
  silkscreen extent -0.65,0 4.15,4.8
SIP1-TEST#1 [mm]
SIP1-TEST#2 [mm]
  round 0.1 smd: 1(0,0)
SIP1-TEST#3 [mm]
  round 1 smd: 1(0,0)
  silkscreen extent -0.7,-0.7 0.7,0.7
SIP2-2.54#1 [mm]
  rect 1.7x1.7 hole 0.9: 1(1.27,0)
  round 1.7 hole 0.9: 2(-1.27,0)
  silkscreen extent -2.54,-1.27 2.54,1.27
SIP2-2.54#2 [mm]
  rect 1.5x1.5 hole 0.9: 1(1.27,0)
  round 1.5 hole 0.9: 2(-1.27,0)
  silkscreen extent -2.54,-1.27 2.54,1.27
SIP10-2.0 [mm]
  rect 1.4x1.4 hole 0.75: 1(9,0)
  round 1.4 hole 0.75: 2(7,0) 3(5,0) 4(3,0) 5(1,0) 6(-1,0) 7(-3,0) 8(-5,0) 9(-7,0) 10(-9,0)
  silkscreen extent -10,-1 10,1
SIP10-2.54MM-SMD [mm]
  rect 4.5x0.9 smd: 1(0,-11.43) 2(0,-8.89) 3(0,-6.35) 4(0,-3.81) 5(0,-1.27) 6(0,1.27) 7(0,3.81) 8(0,6.35) 9(0,8.89) 10(0,11.43)
SMD3225-4 [mm]
  rect 1.4x1.1 smd: 1(-1.3,-0.825) 2(1.3,-0.825) 3(1.3,0.825) 4(-1.3,0.825)
  silkscreen extent -2.2,-1.6 2.2,1.6
SMD4015-2 [mm]
  rect 1x1.8 smd: 1(-2,0) 2(2,0)
  silkscreen extent -2.05,-1.3 2,1.3
SMD-C [mil]
  rect 80x100 smd: 1(-106.5,0) 2(106.5,0)
  silkscreen extent -161,-71 159,71
SOD-123-1 [mm]
  rect 1.5x1.4 smd: 1(-2,0) 2(2,0)
  silkscreen extent -2,-1.5 2,1.5
SOIC-8P [mm]
  rect 0.6x2 smd: 1(-1.905,-2.794)
  oval 0.6x2 smd: 2(-0.635,-2.794) 3(0.635,-2.794) 4(1.905,-2.794) 5(1.905,2.794) 6(0.635,2.794) 7(-0.635,2.794) 8(-1.905,2.794)
  silkscreen extent -2.54,-1.6 2.54,1.6
son-8p [mm]
  rect 3.4x4 smd: 0(0,0)
  rect 1.2x0.45 smd: 1(-3.2,1.905) 2(-3.2,0.635) 3(-3.2,-0.635) 4(-3.2,-1.905) 5(3.2,-1.905) 6(3.2,-0.635) 7(3.2,0.635) 8(3.2,1.905)
  silkscreen extent -4.1,-3 3.32,3.02
SOT-23-3P [mm]
  rect 1x1.29 smd: 1(-0.952,-1.166) 2(0.953,-1.166)
  rect 1x1.47 smd: 3(0.013,1.166)
  silkscreen extent -1.77,-1.09 1.77,1.19
SOT-23-5P [mm]
  rect 0.508x1.4 smd: 1(-0.952,-1.4) 2(-0.013,-1.4) 3(0.953,-1.4) 4(0.952,1.4) 5(-0.953,1.4)
  silkscreen extent -1.81,-1.3 1.79,1.3
SOT-23-8P [mm]
  rect 0.3x1.1 smd: 1(-0.975,-1.575)
  oval 0.3x1.1 smd: 2(-0.325,-1.575) 3(0.325,-1.575) 4(0.975,-1.575) 5(0.975,1.575) 6(0.325,1.575) 7(-0.325,1.575) 8(-0.975,1.575)
  silkscreen extent -1.5,-0.88 1.5,0.88
SOT-223-6 [mm]
  rect 0.5x2.2 smd: 1(0,0) 2(1.27,0) 3(2.54,0) 4(3.81,0) 5(5.08,0)
  rect 4x3 smd: 3(2.54,6.2)
  silkscreen extent -0.86,1.4 5.94,4.3
TSSOP-16P [mm]
  oval 0.3x1.6 smd: 1(-2.275,-3.15) 2(-1.625,-3.15) 3(-0.975,-3.15) 4(-0.325,-3.15) 5(0.325,-3.15) 6(0.975,-3.15) 7(1.625,-3.15) 8(2.275,-3.15) 9(2.275,3.15) 10(1.625,3.15) 11(0.975,3.15) 12(0.325,3.15) 13(-0.325,3.15) 14(-0.975,3.15) 15(-1.625,3.15) 16(-2.275,3.15)
  silkscreen extent -2.7,-2.1 2.7,2.1
USB-MIN-F [mm]
  rect 0.5x2 smd: 1(1.65,-3.25) 2(0.85,-3.25) 3(0.05,-3.25) 4(-0.75,-3.25) 5(-1.55,-3.25)
  rect 3x1.8 smd: 6(5.05,-2.25) 7(5.05,3.25) 8(-4.95,-2.25) 9(-5.05,3.25)
  round 1.3 hole 1.2: ""(-2.15,0.75) ""(2.25,0.75)
  silkscreen extent -3.8,-3.05 3.9,6.55
VLF3010A [mm]
  rect 1.2x1.6 smd: 1(-1.45,0) 2(1.45,0)
  silkscreen extent -2.25,-1.4 2.2,1.4

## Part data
C1 C2 C6 C7 C13 C15 C16 C18 C21 C29 C56 C62 C73 C74 C76 C77 C78 C79 C81 C82 C85 C100 C101 C102 C105 C206: library part "Cap Pol1", "Polarized Capacitor (Radial)"
C3 C4 C5 C8 C9 C10 C11 C12 C14 C17 C19 C20 C22 C23 C24 C25 C26 C27 C28 C30 C31 C32 C33 C34 C35 C36 C37 C38 C39 C40 C41 C42 C43 C44 C45 C46 C47 C48 C49 C50 C51 C52 C53 C54 C55 C57 C58 C59 C60 C61 C63 C64 C65 C66 C67 C68 C69 C70 C71 C72 C75 C80 C83 C87 C88 C89 C103 C104 C106 C107 C108 C109 C110 C111 C200 C201 C202 C203 C208 C209 C210 C211 C220: library part Cap, "Capacitor"
D1 D4: library part Diode, "Default Diode"
D2: library part "Diode 10TQ045", "Schottky Rectifier"
D3 D6 D7 D8 D9 D10 D11 D12 D13 D14: library part LED0, "Typical INFRARED GaAs LED"
D5: library part "Diode 10TQ035", "Schottky Rectifier"
JP6: library part JUMPER
L1 L2 L3 L4 L5 L6 L7 L8: library part "Inductor Iron", "Magnetic-Core Inductor"
L9 L11: library part Inductor, "Inductor"
P1: library part "Header 10", "Header, 10-Pin"
P3 P4: "Header, 10-Pin"
Q1: library part MOSFET-P, "P-Channel MOSFET"
R1 R2 R3 R4 R5 R6 R7 R8 R9 R10 R11 R12 R13 R14 R15 R16 R17 R18 R19 R20 R21 R22 R23 R24 R25 R26 R27 R28 R29 R30 R31 R32 R33 R34 R35 R36 R37 R38 R39 R40 R41 R42 R43 R44 R45 R46 R47 R48 R49 R50 R51 R52 R53 R54 R55 R56 R57 R58 R59 R62 R63 R64 R65 R66 R67 R68 R69 R70 R71 R72 R73 R75 R76 R77 R78 R79 R80 R81 R82 R83 R84 R85 R86 R87 R89 R90 R91 R92 R93 R94 R95 R96 R97: library part Res1, "Resistor"
TP1 TP2 TP3 TP4 TP5 TP6 TP8 TP9 TP13: library part TextPoint
U4: library part ASDM1-12.000MHZ
U8: library part TPS62260DDCT
U9: library part TPS79533
U12: library part TPS61041
U13: library part Audio_2
Y1: library part XTAL-4

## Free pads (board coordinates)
  round 4 hole 2: ""(16.2,82.325) ""(36.95,82.3)

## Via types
v1: diameter 0.381, hole 0.229, Top Layer to Bottom Layer, 549 vias
v2: diameter 0.508, hole 0.305, Top Layer to Bottom Layer, 42 vias
v3: diameter 0.381, hole 0.203, Top Layer to Bottom Layer, 16 vias

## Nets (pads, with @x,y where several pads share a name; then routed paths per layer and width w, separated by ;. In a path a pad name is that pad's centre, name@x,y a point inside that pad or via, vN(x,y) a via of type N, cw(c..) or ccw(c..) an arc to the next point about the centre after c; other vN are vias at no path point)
430_P2.6_INT0: P3.2 U11.5 | length 41.8
  Top Layer w0.25: v1(20.125,40.6) v1(23.8,40.6) ; v2(45.1,26.4) 47,24.5 v2(47,23.8)
  POW w0.25: v1(23.8,40.6) v3(38.25,40.6)
  Bottom Layer w0.25: v1(20.125,40.6) U11.5@20.125,41.7 ; v3(38.25,40.6) 39,39.85 39,37.7 44.8,31.9 44.8,26.7 v2(45.1,26.4) v2@45.14,26.36 ; v2(47,23.8) 47,23 47.11,22.89 P3.2@48.26,22.89
AGND: C28.1 C29.2 C30.1 C31.1 C40.1 C41.1 C42.1 C59.1 C60.1 C61.1 C69.1 C70.1 C71.1 L8.2 U5.A1 U5.B6 U5.H13 U5.J12 | length 49.7
  Top Layer w0.114: v1(15.225,60.275) 15.329,60.379 17.546,60.379 17.943,60.775 U5.B6@17.95,60.775
  Top Layer w0.254: v1(11.825,63.65) 12.2,63.275 C71.1@12.525,63.275 ; v1(17.15,56.3) U5.A1@17.15,56.775 ; U5.H13@22.75,66.375 v1(23.175,65.95) U5.J12@23.55,65.575 ; C30.1@23.2,70.95 C31.1@23.2,69.95 C41.1@24.35,69.95 ; C30.1@23.2,71 C42.1@24.325,71
  Top Layer w0.305: C41.1@24.35,69.95 C42.1@24.35,70.95 24.35,71.45 24.857,71.957 26.257,71.957 27.025,72.725 28.674,72.725 L8.2@29.175,72.224
  POW w0.254: v1(15.325,64.3) 15.325,65.45 15.675,65.8 15.825,65.8 ; v1(16.376,67.578) 15.825,67.027 15.825,65.8 ; v1(23.175,65.95) 22.55,66.575 17.925,66.575 17.15,65.8 15.825,65.8
  Bottom Layer w0.254: v1(11.825,63.65) 12.495,64.32 15.655,64.32 C61.1@15.68,64.295 ; C61.1@15.705,64.32 C61.1@15.925,64.1 ; C60.1@15.825,67.325 16.123,67.325 v1(16.376,67.578) ; C61.1@15.875,64.1 C28.1@15.875,62.925 15.6,62.925 15.225,62.55 15.225,61.903 v1(15.225,60.275) 15.225,60.15 C70.1@15.875,59.5 16.45,58.925 C69.1@17.125,58.925 v1@17.125,56.325 ; v1@16.443,67.578 16.443,67.818 16.75,68.125 C59.1@17.6,68.125 ; C29.2@23,69.675 C29.2@23.1,69.675 ; C29.2@23,69.825 23.7,69.125 23.7,66.475 v1(23.175,65.95) ; C29.2@23.1,69.775 24.575,69.775 C40.1@24.8,69.775
  other v1: 23.85,69.975
AIC_MODE_SEL: R16.2 U2.12 | length 2.9
  Bottom Layer w0.229: U2.12@42.4,66.775 42.4,67.225 42.875,67.7 R16.2@42.875,69.45
ANA_LDO_OUT: C28.2 C69.2 C70.2 U5.B7 U5.B9 U5.C7 | length 8.2
  Top Layer w0.114: v1(16.575,62) 16.554,61.979 17.314,61.979 17.546,62.211 17.546,62.771 U5.B9@17.95,63.175
  Top Layer w0.254: U5.B7@17.95,61.575 v1(18.35,61.575) U5.C7@18.75,61.575
  GND w0.114: v1@16.55,61.975 v1(16.575,62)
  Bottom Layer w0.114: C28.2@15.875,61.925 15.95,62 v1(16.575,62)
  Bottom Layer w0.254: C28.2@15.875,61.925 C70.2@15.875,60.5 C69.2@17.125,60.5 ; C69.2@17.125,60.525 17.15,60.525 18.2,61.575 v1(18.35,61.575)
C5535_INT0: R36.1 U5.C2 U11.12 | length 21
  Top Layer w0.114: U5.C2@18.75,57.575 18.354,57.179 18.354,56.223 20.315,54.262 25.388,54.262 v1(25.475,54.175) ; v1(20.125,49.15) 20.125,49.825 20.975,50.675 23.975,50.675 v1(24.175,50.875)
  Bottom Layer w0.114: U11.12@20.125,48 v1(20.125,49.15) ; v1(24.175,50.875) 24.175,51.1 25.475,52.4 v1(25.475,54.175) 25.5,54.2 R36.1@25.5,55.5
CLK_SEL: JP5.2 R5.2 U5.D1 | length 8.4
  Top Layer w0.114: U5.D1@19.55,56.775 19.55,56.025 20.25,55.325 v1@20.375,55.325
  POW w0.114: JP5.2@15.88,53.375 15.88,54.605 16.6,55.325 v1(20.425,55.325)
  Bottom Layer w0.114: v1(20.425,55.325) 20.625,55.325 R5.2@20.825,55.525
CLKIN: R31.1 R32.2 U5.C1 | length 23
  Top Layer w0.114: U5.C1@18.75,56.775 18.75,56.15 20.362,54.538 24.425,54.538 ; 24.426,54.539 34.861,54.539 v1@34.95,54.45
  Bottom Layer w0.114: v1@34.925,54.425 34.9,54.45 34.9,58.8 R32.2@34.925,58.825 R31.1@36,58.825
  other v1: 34.925,54.45
CLKOUT: R30.2 TP3.1 U5.A2 | length 7.2
  Top Layer w0.114: R30.2@13.55,54.65 13.975,55.075 15.7,55.075 16.125,55.5 16.125,57.4 16.3,57.575 ; TP3.1@15.2,57.2 15.575,57.575 16.3,57.575 ; U5.A2@17.15,57.575 16.3,57.575
CPU_CLK_12MHZ: R23.2 R31.2 | length 1.1
  Bottom Layer w0.114: R31.2@36,59.825 R23.2@37.1,59.825
CVDD: C32.2 C33.2 C34.2 C35.2 C36.2 C37.2 C38.2 C39.2 C46.2 C47.2 C48.2 C49.2 C50.2 C51.2 C52.2 C53.2 C54.2 C55.2 JP6.1 R90.2 U3.2 U5.C11 U5.D3 U5.D11 U5.F2 U5.G3 U5.H2 U5.K11 U5.K12 U5.L13 U5.M6 U5.M9 U5.N9 | length 64.8
  Top Layer w0.114: U5.D3@19.55,58.375 19.954,57.971 20.026,57.971 20.754,57.971 U5.F2@21.15,57.575
  Top Layer w0.25: U5.C11@18.75,64.775 18.75,64.725 v1(19.075,64.4) ; U5.D11@19.55,64.775 19.6,64.775 v1(19.975,64.4) ; U5.F2@21.15,57.575 21.173,57.575 v1(21.501,57.903) ; v1(21.875,59.65) 21.875,58.45 U5.G3@21.95,58.375 ; U5.G3@21.95,58.45 U5.G3@21.95,58.375 ; 22.249,58.076 22.499,57.826 ; U5.H2@22.75,57.575 22.499,57.826 ; v1(23.226,63.175) v1(25.175,63.175) U5.M9@25.95,63.175 U5.N9@26.75,63.175 26.75,63.202 v1(27.076,63.528) ; U5.K11@24.35,64.775 U5.K12@24.35,65.575 ; v1(24.775,66.05) U5.L13@25.099,66.374 ; U5.L13@25.099,66.375 U5.L13@25.15,66.375 ; U5.M6@25.95,60.775 v1(26.25,60.475) ; v1(33.125,55.65) v1(34.525,55.65) v1(35.725,55.65) ; U5.G3@21.95,58.375 22.499,57.826
  POW w0.25: v1(26.25,60.475) 26.5,60.225 26.5,56.6 27.45,55.65 v1(30.7,55.65)
  Bottom Layer w0.25: C35.2@19.125,62.375 C35.2@19.15,62.35 ; C37.2@19.175,65.95 19.25,65.875 19.25,64.75 19.6,64.75 19.875,64.475 v1@19.875,64.4 ; C37.2@19.175,66.025 C32.2@19.175,67.325 ; v1(19.975,64.4) 19.975,63.925 19.7,63.65 C53.2@19.325,63.65 19.325,62.175 19.626,62.175 19.826,62.175 20.825,62.175 C55.2@20.875,62.175 C54.2@22.375,62.175 ; v1(21.501,57.903) 21.553,57.903 22.275,58.625 C38.2@22.325,58.625 ; C38.2@22.175,58.675 22.225,58.675 22.525,58.675 23,59.15 23,59.403 23,59.7 ; C49.2@22.325,59.675 C49.2@22.325,59.825 22.45,59.7 23,59.7 ; v1(24.35,65.15) 23.55,65.15 C48.2@23.525,65.125 ; v1@24.72,66.08 24.35,66.45 C36.2@24.35,66.6 24.35,66.5 23.525,65.675 C48.2@23.525,65.125 ; v1(25.175,63.175) 25.275,63.075 25.625,63.075 25.925,63.075 26.25,62.75 v1(26.25,60.475) 25.875,60.85 C46.2@25.625,60.85 ; v1(27.076,63.528) 27.125,63.577 27.125,63.828 C51.2@27.125,64.5 ; v1(30.7,55.65) C39.2@32.125,55.65 ; 31.65,55.65 C39.2@32.25,55.65 ; C39.2@32.45,55.65 v1(33.125,55.65) ; R90.2@33.875,57.775 34.125,57.775 34.525,57.375 v1(34.525,55.65) ; C54.2@22.375,62.175 23.226,63.026 v1(23.226,63.175) 23.226,64.826 C48.2@23.525,65.125 ; C54.2@22.375,62.175 C54.2@22.35,62.15 23,61.5 23,59.7
  Bottom Layer w0.381: v1(35.725,55.65) 40.78,55.65 ; JP6.1@41.393,55.012 41.403,55.002 41.375,54.975 41.375,52.9 41.925,52.35 U3.2@42.7,52.35
DSP_LDO_OUT: R8.1 U5.A13 | length 27.3
  Top Layer w0.203: v1(26.52,68.555) 28.095,68.555 29.825,66.825 v1(31.95,66.825)
  Top Layer w0.25: v1(16.751,66.375) U5.A13@17.15,66.375
  POW w0.25: v1(16.751,66.375) 19.451,69.075 26,69.075 v1(26.52,68.555)
  Bottom Layer w0.114: v1(31.95,66.825) v1@31.95,66.925
  Bottom Layer w0.203: v1(31.95,66.825) 31.909,66.784 31.909,63.666 32.425,63.15 32.425,61.127 32.273,60.975 32.273,58.277 R8.1@32.775,57.775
